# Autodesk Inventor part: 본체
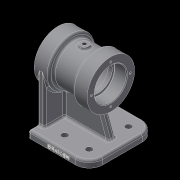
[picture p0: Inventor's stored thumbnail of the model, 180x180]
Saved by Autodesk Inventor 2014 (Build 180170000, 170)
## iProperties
Created: 2020-06
Part Number: 본체
Material: Generic
Document SubType Name: Modeling
Designer: kh
Density: 1 g/cm^3
Appearance: Default
Author: kh
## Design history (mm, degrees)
sketch "Sketch1"
  geometry: L1 (-45, 49)-(25, 49); L2 (45, 29)-(45, -29); L3 (25, -49)-(-45, -49); L4 (-45, -49)-(-45, 49); L5 (-45, 49)-(45, -49); L6 (45, 49)-(-45, -49); A1 r 20 centre (25, 29) between (45, 29) and (25, 49); A2 r 20 centre (25, -29) between (25, -49) and (45, -29); 1 further point
  constraints: 12 end point, 4 point on circle, 4 point on line, 4 tangent, 2 centre point, 2 midpoint, 2 parallel, 1 equal radius, 1 horizontal, 1 perpendicular
  dimensions: "d0" = 90 distance of L1.start L6.start; "d1" = 98 distance of L3.end L1.start; "d2" = 20 radius of A1
extrude "Extrusion1" new body sketch "Sketch1" distance "d3" = 10; taper "d4" = 0 deg
workplane "Work Plane1"
sketch "Sketch7"
  geometry: L1 (-25, 10)-(45, 10) reference; L2 (-25, 10)-(-45, 10) reference; L3 (-45, 0)-(-45, 10) reference; L4 (45, 0)-(45, 10) reference; L5 (45, 0)-(-25, 0) reference; L6 (-45, 0)-(-25, 0) reference; L7 (50, 115)-(28, 115); L8 (28, 115)-(28, 109); L9 (28, 109)-(-6, 109); L10 (-6, 109)-(-6, 115); L11 (-6, 115)-(-28, 115); L12 (-28, 115)-(-28, 80); L13 (-28, 80)-(50, 80); L14 (50, 80)-(50, 115); 1 further point
  constraints: 16 end point, 6 parallel, 1 collinear, 1 perpendicular
  dimensions: "d28" = 80 distance between parallel lines of L5 L13; "d29" = 5 distance between parallel lines of L4 L14; "d30" = 70 diameter of L7 L13; "d31" = 58 diameter of L9 L13; "d32" = 70 diameter of L11 L13; "d33" = 22 distance of L7.start L7.end; "d34" = 22 distance of L10.end L11.end; "d35" = 78 distance between parallel lines of L12 L14
revolve "Revolution1" sketch "Sketch7" stored, may be unused: angle "d36" = 90 deg
sketch "Sketch8"
  geometry: L1 (10, 98)-(10, 0) reference; L2 (80, 84)-(10, 84); L3 (80, 14)-(10, 14); L4 (10, 84)-(10, 14); A1 r 35 centre (80, 49) between (80, 14) and (80, 84) reference; 1 further point
  constraints: 6 end point, 2 point on circle, 2 point on line, 2 tangent, 1 collinear
  dimensions: "d37" = 35 vertical distance of point (0, 49) L2.end; "d38" = 35 vertical distance of L3.end point (0, 49)
extrude "Extrusion5" join sketch "Sketch8" distance "d39" = 10; taper "d40" = 0 deg
sketch "Sketch9"
  geometry: L1 (-6, 51)-(28, 51) reference; L2 (-28, 45)-(-6, 45) reference; L3 (-6, 45)-(-6, 115) reference; L4 (-28, 45)-(-28, 115) reference; L5 (-25, 10)-(45, 10) reference; L6 (-25, 10)-(-45, 10) reference; L7 (-17.261, 45)-(-30, 10); 1 further point
  constraints: 2 end point, 2 point on line
  dimensions: "d41" = 15 distance of L6.end L7.end; "d42" = 70 deg angle of L5 L7
feature "Rib2" sketch "Sketch9" dims "d43" = 1, "d44" = 10, "d45" = 0, "d46" = 0, "d47" = 1, "d48" = 1
sketch "Sketch10"
  geometry: L1 (50, 45)-(50, 115) reference; L2 (28, 115)-(50, 115) reference; L3 (-6, 109)-(28, 109) reference; L4 (-28, 115)-(-6, 115) reference; L5 (-28, 45)-(-28, 115) reference; L6 (-28, 45)-(-17.261, 45) reference; L7 (45, 45)-(50, 45) reference; L8 (50, 80)-(-28, 80); L9 (50, 103.5)-(32.3, 103.5); L10 (32, 103.2)-(32, 100); L11 (32, 100)-(26, 100); L12 (26, 100)-(26, 103); L13 (26, 103)-(-4, 103); L14 (-4, 103)-(-4, 100); L15 (-4, 100)-(-10, 100); L16 (-10, 100)-(-10, 103.2); L17 (-10.3, 103.5)-(-28, 103.5); A1 r 0.3 centre (32.3, 103.2) between (32.3, 103.5) and (32, 103.2); A2 r 0.3 centre (-10.3, 103.2) between (-10, 103.2) and (-10.3, 103.5); 3 further points
  constraints: 20 end point, 7 parallel, 6 point on line, 4 point on circle, 4 tangent, 2 centre point, 2 midpoint, 2 perpendicular, 1 equal radius
  dimensions: "d49" = 47 diameter of L9 L8; "d50" = 40 diameter of L11 L8; "d51" = 46 diameter of L13 L8; "d52" = 40 diameter of L15 L8; "d53" = 47 diameter of L17 L8; "d54" = 18 distance of L9.start point (32, 103.5); "d55" = 18 distance of point (-10, 103.5) L17.end; "d56" = 30 distance of L12.end L13.end; "d57" = 6 distance of L14.end L15.end; "d58" = 0.3 radius of A1
revolve "Revolution2" sketch "Sketch10" stored, may be unused: angle "d59" = 90 deg
sketch "Sketch12"
  geometry: C1 r 23.5 at (0, 0) reference; 2 further points
  constraints: 1 horizontal alignment
  dimensions: "d75" = 28.5 distance of C1.centre point (-28.5, 0)
hole "Hole2" sketch "Sketch12" at (-28.5, 0) diameter "d76" = 3.242; stored, may be unused: countersink angle "d80" = 90 deg, drill point angle "d82" = 118 deg; dims "d77" = 10, "d78" = 4, "d79" = 2, "d81" = 12
pattern_circular "Circular Pattern1" dims angle "d84" = 360 deg
workplane "Work Plane3"
mirror "Mirror1"
sketch "Sketch13"
  geometry: A1 r 20 centre (25, -29) between (25, -49) and (45, -29) reference; 2 further points
  constraints: 1 coincident
hole "Hole3" sketch "Sketch13" at (25, -29) diameter "d87" = 9; stored, may be unused: countersink angle "d91" = 90 deg, drill point angle "d93" = 118 deg; dims "d88" = 10, "d89" = 4, "d90" = 2, "d92" = 12
pattern_linear "Rectangular Pattern1" dims "d96" = 36, "d99" = 58
fillet "Fillet1" dims "d100" = 3
fillet "Fillet2" dims "d101" = 3
fillet "Fillet3" dims "d102" = 3
chamfer "Chamfer1" distance "d103" = 1; stored, may be unused: second distance "d104" = 2, angle "d105" = 45 deg
sketch "Sketch14"
  geometry: L1 (67, 0)-(0, 0) reference; L2 (-3, 7)-(-3, 0) reference; 2 further points
  constraints: 1 other
  dimensions: "d106" = 45 distance from line of point (42, 4) L2; "d107" = 4 distance from line of L1 point (42, 4)
emboss "Emboss1" sketch "Sketch14" dims "d0" = 90, "d1" = 98, "d2" = 20, "d108" = 0.5, "d109" = 0
workplane "Work Plane4"
sketch "Sketch15"
  geometry: L1 (-50, 24.5)-(-50, -24.5) reference; L2 (3, 29)-(-25, 29) reference; C1 r 6 at (-11, 0); 3 further points
  constraints: 2 horizontal alignment, 2 midpoint, 1 centre point, 1 vertical alignment
  dimensions: "d111" = 12 diameter of C1
extrude "Extrusion7" join sketch "Sketch15" stored distance "d112" = 3; taper "d113" = 0 deg
hole "Hole4" diameter "d116" = 5.188; stored, may be unused: countersink angle "d120" = 90 deg, drill point angle "d122" = 118 deg; dims "d114" = 10, "d115" = 10, "d117" = 10, "d118" = 4, "d119" = 2, "d121" = 16.5
fillet "Fillet4" dims "d123" = 3
body "Solid1"
node "Projected Loop3"
other parameters: "d9" = 5, "d110" = 112
